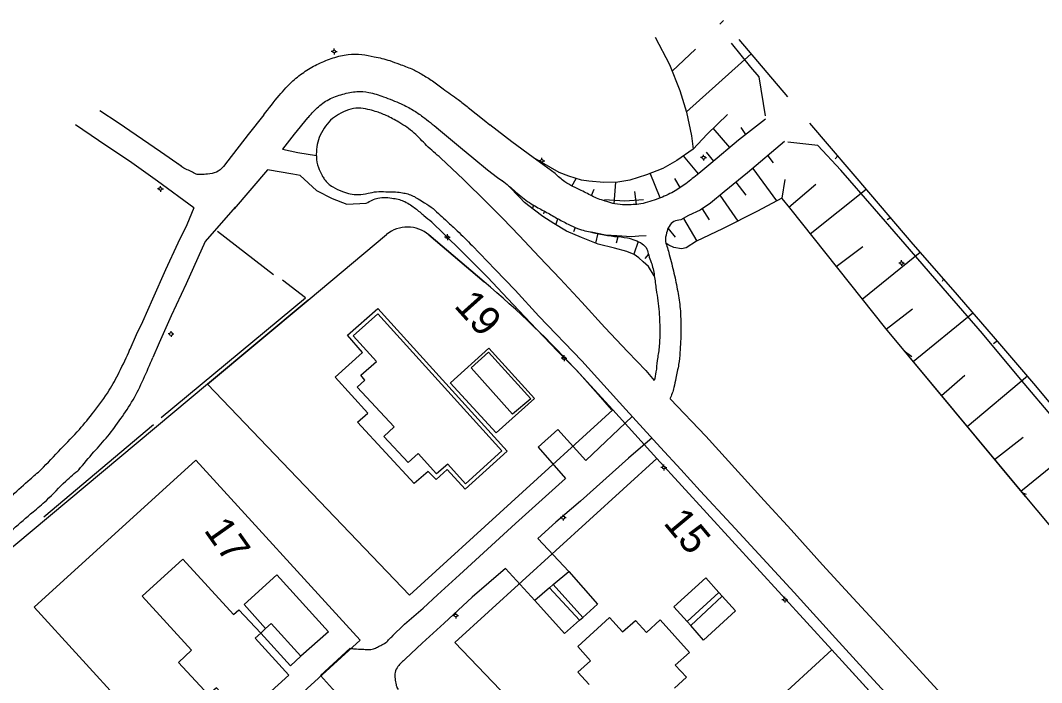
# Model space of a CAD drawing. Extents: x 1517229 to 1518128, y 6494851 to 6495271.
# Drawn here: x 1517875.8 to 1518015.9, y 6495180.1 to 6495271.1 of the extents above; entities that cross this region are included whole.
import ezdxf

# ---------------------------------------------------------------- set-up
doc = ezdxf.new("R2010")
doc.units = 0
doc.layers.add('Karta', color=7, linetype='Continuous')

msp = doc.modelspace()

# ---------------------------------------------------------------- linework, layer by layer
at = {"layer": 'Karta'}
for p, q in [((1517972.3, 6495271.08), (1517971.79, 6495270.57)), ((1517918.65, 6495266.82), (1517918.45, 6495266.82)), ((1517918.85, 6495267.02), (1517918.85, 6495267.22)), ((1517919.05, 6495266.82), (1517919.25, 6495266.82)), ((1517965.24, 6495264.1), (1517968.44, 6495267.14)), ((1517918.85, 6495266.62), (1517918.85, 6495266.42)), ((1517967.2, 6495258.52), (1517976.06, 6495266.51)), ((1517973.17, 6495253.63), (1517970.86, 6495256.26)), ((1517975.35, 6495255.42), (1517974.71, 6495256.35)), ((1517981.11, 6495254.39), (1517985.21, 6495253.96)), ((1517970.95, 6495251.76), (1517969.97, 6495253)), ((1517904.26, 6495251.79), (1517903.65, 6495251)), ((1517947.15, 6495251.8), (1517946.95, 6495251.8)), ((1517947.35, 6495252), (1517947.35, 6495252.2)), ((1517947.35, 6495251.6), (1517947.35, 6495251.4)), ((1517947.55, 6495251.8), (1517947.75, 6495251.8)), ((1517968.84, 6495250.02), (1517966.78, 6495252.47)), ((1517969.35, 6495252.23), (1517969.15, 6495252.23)), ((1517969.55, 6495252.43), (1517969.55, 6495252.63)), ((1517969.55, 6495252.03), (1517969.55, 6495251.83)), ((1517969.75, 6495252.23), (1517969.95, 6495252.23)), ((1517978.36, 6495252.5), (1517979.11, 6495251.5)), ((1517987.98, 6495252.48), (1517987.62, 6495252.06)), ((1517909.68, 6495250.58), (1517905.11, 6495245.18)), ((1517963.57, 6495246.69), (1517962.21, 6495250.08)), ((1517976.3, 6495250.76), (1517979.58, 6495246.28)), ((1517951.46, 6495248.32), (1517952.08, 6495249.38)), ((1517957.27, 6495245.91), (1517957.5, 6495248.86)), ((1517966.35, 6495248.11), (1517965.6, 6495249.35)), ((1517973.99, 6495248.86), (1517975.33, 6495247.06)), ((1517981.27, 6495245.42), (1517984.94, 6495248.57)), ((1517894.81, 6495247.93), (1517894.61, 6495247.93)), ((1517895.01, 6495248.13), (1517895.01, 6495248.33)), ((1517895.01, 6495247.73), (1517895.01, 6495247.53)), ((1517895.21, 6495247.93), (1517895.41, 6495247.93)), ((1517954.15, 6495247.01), (1517954.52, 6495247.89)), ((1517960.36, 6495245.81), (1517960.13, 6495247.6)), ((1517984.17, 6495241.77), (1517991.88, 6495247.92)), ((1517971.79, 6495247.06), (1517974.23, 6495243.5)), ((1517946.2, 6495245.71), (1517946.03, 6495245.16)), ((1517947.66, 6495244.9), (1517947.56, 6495244.5)), ((1517969.34, 6495245.22), (1517970.3, 6495243.7)), ((1517949.27, 6495243.01), (1517949.57, 6495243.83)), ((1517966.78, 6495243.88), (1517968.63, 6495240.76)), ((1517995.23, 6495243.99), (1517994.76, 6495243.67)), ((1517902.85, 6495242.13), (1517910.53, 6495236.18)), ((1517915.28, 6495232.66), (1517926.05, 6495241.66)), ((1517939.46, 6495235.17), (1517931.85, 6495241.64)), ((1517931.85, 6495241.64), (1517939.46, 6495235.17)), ((1517934.39, 6495241.51), (1517934.39, 6495241.71)), ((1517951.94, 6495242.63), (1517951.72, 6495242.02)), ((1517964.67, 6495242.51), (1517965.64, 6495241.3)), ((1517934.19, 6495241.31), (1517933.99, 6495241.31)), ((1517934.39, 6495241.11), (1517934.39, 6495240.91)), ((1517934.59, 6495241.31), (1517934.79, 6495241.31)), ((1517957.76, 6495241.36), (1517957.55, 6495240.49)), ((1517960.58, 6495240.72), (1517959.96, 6495238.98)), ((1517961.97, 6495238.98), (1517961.48, 6495238.38)), ((1517987.76, 6495237.27), (1517991.4, 6495240.03)), ((1517991.31, 6495232.8), (1517999.27, 6495239.27)), ((1517996.53, 6495237.75), (1517996.33, 6495237.75)), ((1517996.73, 6495237.95), (1517996.73, 6495238.15)), ((1517996.73, 6495237.55), (1517996.73, 6495237.35)), ((1517996.93, 6495237.75), (1517997.13, 6495237.75)), ((1518002.5, 6495235.58), (1518002.3, 6495235.24)), ((1517915.28, 6495232.66), (1517901.45, 6495221.1)), ((1517920.68, 6495227.84), (1517924.86, 6495231.52)), ((1517994.6, 6495228.68), (1517998.22, 6495231.48)), ((1517998.31, 6495224.21), (1518006.52, 6495230.93)), ((1517896.26, 6495228.01), (1517896.06, 6495228.01)), ((1517896.46, 6495228.21), (1517896.46, 6495228.41)), ((1517896.46, 6495227.81), (1517896.46, 6495227.61)), ((1517896.66, 6495228.01), (1517896.86, 6495228.01)), ((1517994.52, 6495228.77), (1518013.17, 6495206.32)), ((1517994.52, 6495228.77), (1518013.7, 6495205.68)), ((1518009.87, 6495227.05), (1518009.33, 6495226.67)), ((1517950.4, 6495224.88), (1517950.4, 6495225.08)), ((1517997.08, 6495225.69), (1517998.14, 6495224.9)), ((1517950.2, 6495224.68), (1517950, 6495224.68)), ((1517950.4, 6495224.48), (1517950.4, 6495224.28)), ((1517950.6, 6495224.68), (1517950.8, 6495224.68)), ((1517957.08, 6495217.57), (1517952.55, 6495222.53)), ((1517952.55, 6495222.53), (1517957.08, 6495217.57)), ((1518002.19, 6495219.54), (1518005.41, 6495222.35)), ((1518005.72, 6495215.29), (1518014.01, 6495222.24)), ((1517901.45, 6495221.1), (1517860.04, 6495186.49)), ((1517901.45, 6495221.1), (1517860.04, 6495186.49)), ((1517901.45, 6495221.1), (1517929.19, 6495192.13)), ((1517929.19, 6495192.13), (1517957.08, 6495217.57)), ((1517957.08, 6495217.57), (1517963.15, 6495210.92)), ((1517878.99, 6495202.9), (1517894.04, 6495215.59)), ((1518009.49, 6495210.76), (1518013.39, 6495213.85)), ((1518013.08, 6495206.44), (1518021.52, 6495213.26)), ((1517935.42, 6495185.63), (1517963.15, 6495210.92)), ((1517963.15, 6495210.92), (1517987.15, 6495184.61)), ((1517877.68, 6495190.48), (1517899.85, 6495210.7)), ((1517899.85, 6495210.7), (1517922.42, 6495185.95)), ((1517963.9, 6495209.67), (1517963.7, 6495209.67)), ((1517964.1, 6495209.87), (1517964.1, 6495210.07)), ((1517964.1, 6495209.47), (1517964.1, 6495209.27)), ((1517964.3, 6495209.67), (1517964.5, 6495209.67)), ((1517950.09, 6495202.78), (1517949.89, 6495202.78)), ((1517950.29, 6495202.98), (1517950.29, 6495203.18)), ((1517950.29, 6495202.58), (1517950.29, 6495202.38)), ((1517950.49, 6495202.78), (1517950.69, 6495202.78)), ((1517948.42, 6495193.16), (1517948.93, 6495193.61)), ((1517952.51, 6495188.68), (1517948.42, 6495193.16)), ((1517952.98, 6495189.08), (1517948.93, 6495193.61)), ((1517967.31, 6495188.5), (1517971.66, 6495192.49)), ((1517971.66, 6495192.49), (1517972.12, 6495191.98)), ((1517967.78, 6495187.99), (1517972.12, 6495191.98)), ((1517980.51, 6495191.51), (1517980.31, 6495191.51)), ((1517980.71, 6495191.71), (1517980.71, 6495191.91)), ((1517980.71, 6495191.31), (1517980.71, 6495191.11)), ((1517980.91, 6495191.51), (1517981.11, 6495191.51)), ((1517900.25, 6495165.74), (1517877.68, 6495190.48)), ((1517935.53, 6495189.54), (1517935.53, 6495189.74)), ((1517935.33, 6495189.34), (1517935.13, 6495189.34)), ((1517935.53, 6495189.14), (1517935.53, 6495188.94)), ((1517935.73, 6495189.34), (1517935.93, 6495189.34)), ((1517952.51, 6495188.68), (1517952.98, 6495189.08)), ((1517952.56, 6495188.64), (1517952.56, 6495188.65)), ((1517967.31, 6495188.5), (1517967.78, 6495187.99)), ((1517909.42, 6495187.56), (1517908.77, 6495186.9)), ((1517922.42, 6495185.95), (1517900.25, 6495165.74)), ((1517960.06, 6495159.9), (1517935.42, 6495185.63)), ((1517987.15, 6495184.61), (1517960.06, 6495159.9)), ((1518012.65, 6495156.65), (1517987.15, 6495184.61))]:
    msp.add_line(p, q, dxfattribs=at)
for points in [[(1517962.91, 6495268.78), (1517964.87, 6495265.03), (1517966.27, 6495261.46), (1517967.21, 6495258.48), (1517967.89, 6495255.25), (1517968.1, 6495253.38)], [(1517974.4, 6495268.48), (1517978.23, 6495263.93), (1517981.09, 6495260.58)], [(1517973.33, 6495267.97), (1517975.97, 6495264.65), (1517977.12, 6495263.33), (1517977.98, 6495257.96)], [(1517897.87, 6495251.08), (1517895, 6495253.05), (1517889.21, 6495257), (1517886.68, 6495258.66)], [(1517937.26, 6495259.13), (1517939.45, 6495257.4), (1517940.2, 6495256.74)], [(1517909.19, 6495258.1), (1517907.06, 6495255.4), (1517904.26, 6495251.79)], [(1517915.19, 6495257.68), (1517913.34, 6495255.46), (1517911.77, 6495253.4), (1517913.86, 6495252.95), (1517916.41, 6495252.52)], [(1517972.83, 6495258.15), (1517970.04, 6495255.46), (1517968.1, 6495253.38), (1517965.87, 6495251.85), (1517963.96, 6495250.74), (1517961.7, 6495249.89), (1517959.41, 6495249.16), (1517957.79, 6495248.87), (1517955.88, 6495248.82), (1517953.79, 6495248.99), (1517952.81, 6495249.16), (1517951.07, 6495249.67), (1517949.71, 6495250.19), (1517946.16, 6495252.23)], [(1517978.04, 6495257.54), (1517974.33, 6495254.61), (1517970.55, 6495251.42), (1517968.89, 6495250.06)], [(1517998.31, 6495240.37), (1517992.51, 6495247.18), (1517984.14, 6495256.98)], [(1517886.5, 6495254.58), (1517883.35, 6495256.72)], [(1517932.91, 6495256.37), (1517936.2, 6495253.64), (1517938.04, 6495252.1), (1517939.89, 6495250.58), (1517941.29, 6495249.49), (1517942, 6495249)], [(1517949.16, 6495250.06), (1517946.16, 6495252.23), (1517943.22, 6495254.4), (1517940.2, 6495256.74)], [(1517899.6, 6495245.34), (1517894.6, 6495249), (1517891.08, 6495251.5), (1517886.5, 6495254.58)], [(1517980.64, 6495254.43), (1517975.57, 6495250.14), (1517972.38, 6495247.55), (1517970.5, 6495245.97), (1517969.06, 6495245.04), (1517967.49, 6495244.27), (1517966.42, 6495243.68)], [(1517997.21, 6495240.37), (1517993, 6495245.2), (1517988.39, 6495250.52), (1517985.24, 6495253.92)], [(1517933.45, 6495252.2), (1517936.62, 6495249.25), (1517939.8, 6495246.06), (1517942.01, 6495243.85), (1517944.26, 6495241.55), (1517947.01, 6495238.58), (1517949.86, 6495235.6)], [(1517914.17, 6495249.79), (1517913.19, 6495249.94), (1517909.68, 6495250.58)], [(1517914.17, 6495249.79), (1517916.41, 6495247.7), (1517918.57, 6495246.62), (1517920.58, 6495245.85), (1517923.25, 6495245.98)], [(1517980.72, 6495249.24), (1517980.29, 6495246.66), (1517976.93, 6495244.87), (1517972.16, 6495242.44), (1517968.59, 6495240.74), (1517967.15, 6495239.85), (1517966.51, 6495239.72), (1517965.49, 6495239.89), (1517964.76, 6495240.23), (1517964.41, 6495240.44)], [(1517962.79, 6495236.02), (1517961.98, 6495237.29), (1517961.26, 6495237.93), (1517960.66, 6495238.49), (1517960.02, 6495238.95), (1517959.04, 6495239.34), (1517957.34, 6495239.8), (1517955.09, 6495240.36), (1517952.79, 6495241.25), (1517950.75, 6495242.14), (1517949.01, 6495243.17), (1517947.48, 6495244.14), (1517946.33, 6495245.04), (1517944.97, 6495246.06), (1517944.33, 6495246.78), (1517942.8, 6495248.36)], [(1517961.3, 6495246.44), (1517958.75, 6495246.27), (1517955.94, 6495246.44)], [(1517980.27, 6495246.64), (1517981.35, 6495245.32), (1517994.52, 6495228.77)], [(1517899.6, 6495245.34), (1517898.64, 6495243.02), (1517897.38, 6495240.49), (1517895.69, 6495236.81), (1517893.9, 6495232.81), (1517892.54, 6495229.7), (1517891.69, 6495227.91), (1517890.8, 6495225.86)], [(1517905.27, 6495245.44), (1517901.17, 6495240.7), (1517898.54, 6495234.91), (1517896.48, 6495230.49), (1517894.85, 6495226.8), (1517893.98, 6495224.8)], [(1517932.03, 6495243.6), (1517936.25, 6495239.46), (1517939.94, 6495235.76), (1517942.64, 6495232.89)], [(1517901.45, 6495221.1), (1517915.28, 6495232.66), (1517926.05, 6495241.66)], [(1517954.11, 6495242.06), (1517956.11, 6495241.63), (1517957.64, 6495241.55), (1517959.64, 6495241.42), (1517960.66, 6495241.51), (1517961.68, 6495241.55)], [(1517955.02, 6495241.86), (1517954.71, 6495240.49), (1517954.71, 6495240.49)], [(1517937.77, 6495240.15), (1517940.95, 6495236.88), (1517943.68, 6495234.03)], [(1518013.04, 6495221.82), (1518007.85, 6495228.06), (1518003.02, 6495233.63), (1517997.21, 6495240.37)], [(1518014.89, 6495221.21), (1518010.22, 6495226.64), (1518003.8, 6495234.09), (1517998.31, 6495240.37)], [(1517895.11, 6495216.54), (1517914.9, 6495232.97), (1517911.74, 6495235.39)], [(1517949.86, 6495235.6), (1517952.86, 6495232.36), (1517956.02, 6495228.9), (1517959.14, 6495225.57), (1517961.62, 6495222.99), (1517962.77, 6495221.61)], [(1517943.68, 6495234.03), (1517946.95, 6495230.45), (1517952.83, 6495224.33), (1517958.87, 6495217.66)], [(1517942.64, 6495232.86), (1517942.64, 6495232.89), (1517946.64, 6495228.67), (1517949.48, 6495225.67), (1517952.15, 6495223.01), (1517955.09, 6495219.7), (1517956.93, 6495217.58)], [(1517924.86, 6495231.52), (1517942.59, 6495211.91), (1517936.81, 6495206.69), (1517934.38, 6495209.4), (1517932.84, 6495208), (1517931.75, 6495209.14), (1517929.81, 6495207.46), (1517922.04, 6495215.92), (1517923.49, 6495217.12), (1517918.97, 6495222.06), (1517922.72, 6495225.46), (1517920.68, 6495227.84)], [(1517921.48, 6495227.76), (1517924.83, 6495230.77), (1517941.87, 6495211.98), (1517936.88, 6495207.44), (1517934.45, 6495210.15), (1517932.9, 6495208.79), (1517930.38, 6495211.58), (1517928.99, 6495210.35), (1517925.66, 6495213.95), (1517927.07, 6495215.24), (1517922.01, 6495220.71), (1517923.07, 6495221.68), (1517922.52, 6495222.34), (1517924.66, 6495224.25), (1517921.48, 6495227.76)], [(1517994.52, 6495228.77), (1518013.25, 6495206.24), (1518013.25, 6495206.23), (1518013.84, 6495205.99)], [(1517934.81, 6495221.31), (1517940.08, 6495226.07), (1517946.34, 6495219.15), (1517941.08, 6495214.43), (1517934.79, 6495221.29)], [(1517937.65, 6495223.35), (1517940.04, 6495225.49), (1517945.85, 6495219.12), (1517943.34, 6495217), (1517937.65, 6495223.35)], [(1518031.27, 6495199.75), (1518027.69, 6495204.15), (1518023.01, 6495210.11), (1518017.83, 6495216.14), (1518013.04, 6495221.82)], [(1518033.04, 6495199.36), (1518027.3, 6495206.38), (1518021.34, 6495213.48), (1518014.89, 6495221.21)], [(1517964.95, 6495219.12), (1517969.84, 6495213.99), (1517974.32, 6495209.08), (1517977.87, 6495205.14), (1517981.56, 6495201.13)], [(1517959.74, 6495216.67), (1517953.37, 6495210.62), (1517949.56, 6495214.91), (1517946.87, 6495212.46), (1517950.61, 6495208.17)], [(1517958.87, 6495217.66), (1517963.65, 6495212.41), (1517966.44, 6495209.41), (1517969.08, 6495206.47), (1517973.35, 6495201.89)], [(1517962.5, 6495213.75), (1517959.24, 6495210.93), (1517952.66, 6495205.06)], [(1517963.15, 6495210.92), (1517987.15, 6495184.61), (1518012.65, 6495156.65)], [(1517950.61, 6495208.17), (1517943.72, 6495201.98), (1517936.03, 6495194.93)], [(1518013.17, 6495206.32), (1518023.48, 6495194.01), (1518031.39, 6495184.5)], [(1517952.66, 6495205.06), (1517949.27, 6495202.14), (1517946.82, 6495199.9), (1517951.08, 6495195.38)], [(1517973.35, 6495201.89), (1517977.69, 6495197.16), (1517981.96, 6495192.49), (1517987.66, 6495186.25)], [(1517981.56, 6495201.13), (1517985.87, 6495196.31), (1517990.08, 6495191.71), (1517994.66, 6495186.79)], [(1517892.51, 6495191.99), (1517898.1, 6495197.09), (1517905.02, 6495189.5), (1517905.77, 6495190.12), (1517908.77, 6495186.9), (1517908, 6495186.22), (1517912.61, 6495181.16), (1517906.31, 6495175.43), (1517902.71, 6495179.4), (1517901.62, 6495178.44), (1517897.5, 6495182.9), (1517899.28, 6495184.6), (1517892.51, 6495191.99)], [(1517946.39, 6495191.38), (1517942.36, 6495195.8), (1517937.81, 6495191.87), (1517933.94, 6495188.29)], [(1517948.93, 6495193.61), (1517951.08, 6495195.38), (1517955.01, 6495190.91), (1517952.98, 6495189.08)], [(1517906.5, 6495190.84), (1517911, 6495194.93), (1517918.09, 6495187.12), (1517914.28, 6495183.76), (1517910.2, 6495188.24), (1517909.42, 6495187.56), (1517906.5, 6495190.84)], [(1517926.78, 6495186.44), (1517928.52, 6495188.16), (1517931.05, 6495190.35), (1517933.02, 6495192.16), (1517936.03, 6495194.93)], [(1517971.66, 6495192.49), (1517969.87, 6495194.53), (1517965.45, 6495190.51), (1517967.31, 6495188.5)], [(1517948.42, 6495193.16), (1517946.39, 6495191.38), (1517950.45, 6495186.89), (1517952.51, 6495188.68)], [(1517972.12, 6495191.98), (1517973.94, 6495190), (1517969.52, 6495185.95), (1517967.78, 6495187.99)], [(1517933.94, 6495188.29), (1517930.92, 6495185.53), (1517928.63, 6495183.37)], [(1517952.29, 6495185.09), (1517956.64, 6495189.05), (1517958.42, 6495187.08), (1517960.19, 6495188.67), (1517961.7, 6495186.99), (1517963.61, 6495188.75), (1517967.63, 6495184.27), (1517965.67, 6495182.52), (1517967.2, 6495180.87), (1517965.54, 6495179.37)], [(1517908.77, 6495186.9), (1517912.84, 6495182.44), (1517914.28, 6495183.76)], [(1517987.66, 6495186.25), (1517992.87, 6495180.52), (1517996.66, 6495176.39), (1518001.2, 6495171.42)], [(1517994.66, 6495186.79), (1517999.17, 6495181.82), (1518004.14, 6495176.43), (1518008.54, 6495171.61)], [(1517927.68, 6495178.87), (1517927.87, 6495178.53), (1517923.16, 6495174.23), (1517916.97, 6495181.1), (1517921.05, 6495184.84)], [(1517953.83, 6495179.86), (1517952.31, 6495181.55), (1517954.05, 6495183.1), (1517952.29, 6495185.09)]]:
    msp.add_lwpolyline(points, dxfattribs=at)
for centre in [(1517918.85, 6495266.82), (1517947.35, 6495251.8), (1517969.55, 6495252.23), (1517895.01, 6495247.93), (1517934.39, 6495241.31), (1517996.73, 6495237.75), (1517896.46, 6495228.01), (1517950.4, 6495224.68), (1517964.1, 6495209.67), (1517950.29, 6495202.78), (1517980.71, 6495191.51), (1517935.53, 6495189.34)]:
    msp.add_circle(centre, 0.2, dxfattribs=at)
for centre, radius, start, end in [((1517928.93, 6495238.2), 4.5, 49.6994, 129.8503), ((1517928.93, 6495238.2), 4.5, 49.6994, 129.8503), ((1517846.58, 6495125.82), 143.47, 42.3829, 49.656), ((1517846.59, 6495125.83), 143.46, 42.3826, 49.6563)]:
    msp.add_arc(centre, radius, start, end, dxfattribs=at)
for points in [[(1517909.19, 6495258.1), (1517911.31, 6495260.77), (1517913.19, 6495262.77), (1517914.89, 6495264.1), (1517916.71, 6495265.13), (1517918.71, 6495265.92), (1517920.77, 6495266.41), (1517922.65, 6495266.41), (1517924.34, 6495266.1), (1517926.47, 6495265.56), (1517927.8, 6495265.07), (1517929.5, 6495264.41), (1517930.89, 6495263.68), (1517932.35, 6495262.77), (1517933.8, 6495261.68), (1517935.86, 6495260.22), (1517937.26, 6495259.13)], [(1517915.19, 6495257.68), (1517916.53, 6495259.07), (1517918.1, 6495260.22), (1517920.04, 6495260.95), (1517921.98, 6495261.31), (1517923.62, 6495261.19), (1517925.62, 6495260.59), (1517928.04, 6495259.62), (1517929.68, 6495258.77), (1517931.01, 6495257.86), (1517933.1, 6495256.22)], [(1517933.5, 6495252.16), (1517931.53, 6495253.92), (1517929.83, 6495255.61), (1517927.71, 6495257.1), (1517926.01, 6495258.01), (1517924.5, 6495258.59), (1517923.47, 6495258.86), (1517922.16, 6495259.04), (1517920.83, 6495258.8), (1517919.44, 6495258.16), (1517918.37, 6495257.37), (1517917.47, 6495256.28), (1517916.8, 6495254.98), (1517916.47, 6495253.7), (1517916.41, 6495252.34), (1517916.68, 6495250.88), (1517917.19, 6495249.79), (1517917.5, 6495249.28), (1517918.65, 6495248.22), (1517920.01, 6495247.58), (1517921.07, 6495247.25), (1517922.16, 6495247.16), (1517923.5, 6495247.34), (1517924.68, 6495247.55), (1517925.92, 6495247.55), (1517927.29, 6495247.52), (1517928.25, 6495247.4), (1517928.95, 6495247.25), (1517930.38, 6495246.58), (1517931.26, 6495246.03), (1517932.44, 6495245.25)], [(1517903.65, 6495251), (1517902.69, 6495250.24), (1517901.48, 6495249.97), (1517900.54, 6495249.92), (1517899.92, 6495249.97), (1517899.22, 6495250.34), (1517898.48, 6495250.66), (1517897.48, 6495251.34)], [(1517968.89, 6495250.06), (1517967.1, 6495248.65), (1517965.44, 6495247.55), (1517963.36, 6495246.61), (1517960.94, 6495245.89), (1517958.81, 6495245.76), (1517957.36, 6495245.89), (1517956.26, 6495246.19), (1517954.43, 6495246.87), (1517952.77, 6495247.72), (1517950.52, 6495248.91), (1517949.16, 6495250.06)], [(1517941.91, 6495249.08), (1517942.8, 6495248.36), (1517944.71, 6495246.74), (1517946.63, 6495245.46), (1517948.2, 6495244.61), (1517949.77, 6495243.72), (1517951.35, 6495242.91), (1517952.54, 6495242.4), (1517953.52, 6495242.14), (1517957.34, 6495241.42), (1517959.09, 6495241.21), (1517960.11, 6495240.91), (1517961.13, 6495240.4), (1517961.77, 6495239.68), (1517962.02, 6495238.83), (1517962.36, 6495237.85), (1517962.79, 6495236.02), (1517963.04, 6495234.1)], [(1517923.25, 6495245.98), (1517924.07, 6495246.4), (1517924.86, 6495246.67), (1517925.98, 6495246.76), (1517927.01, 6495246.64), (1517927.83, 6495246.46), (1517928.55, 6495246.19), (1517929.34, 6495245.73), (1517930.01, 6495245.25), (1517931.16, 6495244.28), (1517932.25, 6495243.43)], [(1517932.44, 6495245.25), (1517934.35, 6495243.46), (1517935.74, 6495242.18), (1517937.77, 6495240.15)], [(1517966.42, 6495243.68), (1517965.49, 6495243.46), (1517964.81, 6495242.78), (1517964.47, 6495241.89), (1517964.34, 6495240.7), (1517964.59, 6495239.85), (1517964.85, 6495238.91)], [(1517964.85, 6495238.91), (1517965.49, 6495236.36), (1517966, 6495233.85), (1517966.34, 6495231.47), (1517966.42, 6495229.3), (1517966.42, 6495227.55), (1517966.3, 6495225.51), (1517966.13, 6495223.81), (1517965.74, 6495221.94), (1517965.49, 6495220.66), (1517964.93, 6495219.09)], [(1517963.04, 6495234.11), (1517963.45, 6495231.04), (1517963.53, 6495228.23), (1517963.45, 6495226.15), (1517963.19, 6495224.36), (1517963.02, 6495222.79), (1517962.77, 6495221.6)], [(1517878.6, 6495209.34), (1517881.35, 6495212.22), (1517883.88, 6495214.9), (1517885.88, 6495217.33), (1517887.98, 6495220.28), (1517889.35, 6495222.75), (1517890.83, 6495225.91)], [(1517883.8, 6495209.34), (1517885.88, 6495211.8), (1517887.77, 6495213.96), (1517889.56, 6495216.38), (1517891.25, 6495218.96), (1517892.67, 6495221.8), (1517893.98, 6495224.8)], [(1517847.48, 6495180.94), (1517850.48, 6495183.16), (1517853.11, 6495184.89), (1517854.85, 6495186.1), (1517856.53, 6495187.26), (1517859.22, 6495189.1), (1517862.16, 6495191.16), (1517866.64, 6495194.63), (1517869.22, 6495196.53), (1517872.32, 6495199.06), (1517874.8, 6495201.22), (1517877.53, 6495203.58), (1517879.37, 6495205.16), (1517882.01, 6495207.8), (1517883.9, 6495209.43)], [(1517861.5, 6495195.05), (1517864.48, 6495197.37), (1517868.01, 6495200.16), (1517872.27, 6495203.64), (1517877.11, 6495208.06), (1517878.64, 6495209.38)], [(1517921.05, 6495184.84), (1517921.66, 6495184.76), (1517922.76, 6495184.71), (1517923.5, 6495184.66), (1517924.26, 6495184.74), (1517924.81, 6495185), (1517925.39, 6495185.32), (1517926.1, 6495185.74), (1517926.55, 6495186.24), (1517926.97, 6495186.61)], [(1517928.63, 6495183.37), (1517927.6, 6495182.34), (1517927.23, 6495181.53), (1517927.21, 6495180.66), (1517927.34, 6495179.84), (1517927.47, 6495179.45), (1517927.63, 6495179.16)]]:
    msp.add_spline(points, degree=3, dxfattribs=at)

# ---------------------------------------------------------------- texts
for s, rotation, p in [('19', 311.858, (1517935.19, 6495231.81)), ('15', 309.7861, (1517963.93, 6495202.01)), ('17', 305.1968, (1517900.88, 6495201.05))]:
    msp.add_text(s, height=4, rotation=rotation, dxfattribs=at).set_placement(p)

doc.saveas('drawing.dxf')
